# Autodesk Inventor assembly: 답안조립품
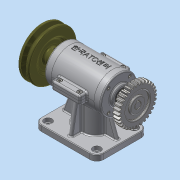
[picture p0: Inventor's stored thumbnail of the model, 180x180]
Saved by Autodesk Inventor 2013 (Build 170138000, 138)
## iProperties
Created: 2015-09
Part Number: 답안조립품
Document SubType Name: Assembly
Designer: dgall
Author: dgall
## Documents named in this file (17)
- C:\Users\dgall\Desktop\350907V1040\답안조립품.iam
- C:\Users\dgall\Desktop\350907V1040\1본체.ipt
- C:\Users\dgall\Desktop\350907V1040\2본체 커버.ipt
- C:\Users\dgall\Desktop\350907V1040\3앞커버.ipt
- C:\Users\dgall\Desktop\350907V1040\4뒤커버.ipt
- C:\Users\dgall\Desktop\350907V1040\5편심축.ipt
- C:\Users\dgall\Desktop\350907V1040\6V-벨트풀리.ipt
- C:\Users\dgall\Desktop\350907V1040\7슬라이드.ipt
- C:\Users\dgall\Desktop\350907V1040\8스퍼기어.ipt
- C:\Users\dgall\Desktop\350907V1040\9베어링 6202.ipt
- C:\Users\dgall\Desktop\350907V1040\10베어링 6201.ipt
- C:\Users\dgall\Desktop\350907V1040\11오일실.ipt
- C:\Users\dgall\Desktop\350907V1040\12M4x0.5x14.ipt
- C:\Users\dgall\Desktop\350907V1040\13M3x0.5x8.ipt
- C:\Users\dgall\Desktop\350907V1040\14멈춤나사.ipt
- C:\Users\dgall\Desktop\350907V1040\15키4x4.ipt
- C:\Users\dgall\Desktop\350907V1040\16가변스프링.ipt
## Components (28 placed, 15 different names)
1. 1본체:1 — 각도:1
2. 2본체 커버:1
3. 3앞커버:1
4. 4뒤커버:1
5. 5편심축:1 — 각도:1
6. 6V-벨트풀리:1
7. 7슬라이드:1
8. 9베어링 6202:1
9. 10베어링 6201:1
10. 11오일실:1
11. 11오일실:2
12. M4x0.5x14:1
13. M4x0.5x14:2
14. M4x0.5x14:3
15. M4x0.5x14:4
16. M3x0.5x8:1
17. M3x0.5x8:2
18. M3x0.5x8:3
19. M3x0.5x8:4
20. M3x0.5x8:5
21. M3x0.5x8:6
22. M3x0.5x8:7
23. M3x0.5x8:8
24. 14멈춤나사:1
25. 14멈춤나사:2
26. 15키4x4:1
27. 15키4x4:2
28. 16가변스프링:1
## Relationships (1: Angle 1)
- 각도:1 [Angle]: 1본체:1 ↔ 5편심축:1
